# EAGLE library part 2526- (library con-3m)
3M (TM) Pak 100 4-Wall Header Source: 3M
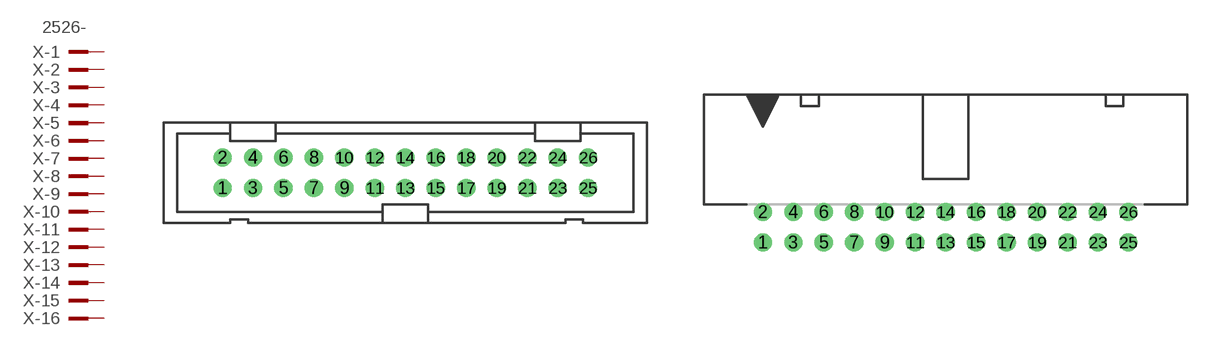
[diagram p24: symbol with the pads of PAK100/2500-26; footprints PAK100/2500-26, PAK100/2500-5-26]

Designator prefix X; gates -1=PINV -2=PIN -3=PIN -4=PIN -5=PIN -6=PIN -7=PIN -8=PIN -9=PIN -10=PIN -11=PIN -12=PIN -13=PIN -14=PIN -15=PIN -16=PIN -17=PIN -18=PIN -19=PIN -20=PIN -21=PIN -22=PIN -23=PIN -24=PIN -25=PIN -26=PIN

## 2526- (OC_FARNELL: unknown; OC_NEWARK: unknown)  [PAK100/2500-26]
1  -1:KL  pas
2  -2:KL  pas
3  -3:KL  pas
4  -4:KL  pas
5  -5:KL  pas
6  -6:KL  pas
7  -7:KL  pas
8  -8:KL  pas
9  -9:KL  pas
10  -10:KL  pas
11  -11:KL  pas
12  -12:KL  pas
13  -13:KL  pas
14  -14:KL  pas
15  -15:KL  pas
16  -16:KL  pas
17  -17:KL  pas
18  -18:KL  pas
19  -19:KL  pas
20  -20:KL  pas
21  -21:KL  pas
22  -22:KL  pas
23  -23:KL  pas
24  -24:KL  pas
25  -25:KL  pas
26  -26:KL  pas

## 2526-5 (OC_FARNELL: 9838392; OC_NEWARK: unknown)  [PAK100/2500-5-26]
Pads as for PAK100/2500-26

## Footprint PAK100/2500-26 (pad centres in mm)
3M (TM) Pak 100 4-Wall Header Straight Source: 3M
drill 1 pad 1.422 round: 1 -15.24,-1.27; 2 -15.24,1.27; 3 -12.7,-1.27; 4 -12.7,1.27; 5 -10.16,-1.27; 6 -10.16,1.27; 7 -7.62,-1.27; 8 -7.62,1.27; 9 -5.08,-1.27; 10 -5.08,1.27; 11 -2.54,-1.27; 12 -2.54,1.27; 13 0,-1.27; 14 0,1.27; 15 2.54,-1.27; 16 2.54,1.27; 17 5.08,-1.27; 18 5.08,1.27; 19 7.62,-1.27; 20 7.62,1.27; 21 10.16,-1.27; 22 10.16,1.27; 23 12.7,-1.27; 24 12.7,1.27; 25 15.24,-1.27; 26 15.24,1.27

## Footprint PAK100/2500-5-26 (pad centres in mm)
3M (TM) Pak 100 4-Wall Header Right Angle Source: 3M
drill 1 pad 1.422 round: 1 -15.24,-1.27; 2 -15.24,1.27; 3 -12.7,-1.27; 4 -12.7,1.27; 5 -10.16,-1.27; 6 -10.16,1.27; 7 -7.62,-1.27; 8 -7.62,1.27; 9 -5.08,-1.27; 10 -5.08,1.27; 11 -2.54,-1.27; 12 -2.54,1.27; 13 0,-1.27; 14 0,1.27; 15 2.54,-1.27; 16 2.54,1.27; 17 5.08,-1.27; 18 5.08,1.27; 19 7.62,-1.27; 20 7.62,1.27; 21 10.16,-1.27; 22 10.16,1.27; 23 12.7,-1.27; 24 12.7,1.27; 25 15.24,-1.27; 26 15.24,1.27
